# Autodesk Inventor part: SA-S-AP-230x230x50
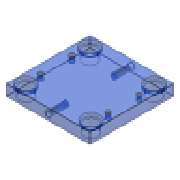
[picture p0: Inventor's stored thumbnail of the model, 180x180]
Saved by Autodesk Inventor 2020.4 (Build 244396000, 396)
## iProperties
Created: 2019-01
Part Number: SA-S-AP-230x230x50
Material: S 55 C
Description: Cavity Plate
Document SubType Name: Modeling
Designer: mel
Standard Revision: 1
Manufacturer: FUTABA
Language: fr-FR
Size Designation: 230x230x50
Categories: <MemberInstance><Categories><Category DisplayName="Moule" InternalName="349578f2-f4d4-4954-8c09-8e99297a61c0" Mnemonic="MOLD"><Category DisplayName="Plaque de m
Density: 7.85 g/cm^3
Appearance: Clear - Blue
IsCustomPart: 1
Author: mel
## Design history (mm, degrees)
sketch "Sketch1"
  geometry: L1 (-115, 115)-(115, 115); L2 (115, 115)-(115, -115); L3 (115, -115)-(-115, -115); L4 (-115, -115)-(-115, 115); 3 further points
  constraints: 8 end point, 2 midpoint, 2 parallel, 1 horizontal, 1 horizontal alignment, 1 perpendicular, 1 vertical alignment
  dimensions: "d123" = 230 distance between parallel lines of L2 L4 (= W_); "d124" = 230 distance between parallel lines of L3 L1 (= L)
extrude "Extrusion1" new body sketch "Sketch1" distance "d20" = 50 (= H_); taper "d30" = 0 deg
sketch "Sketch2"
  geometry: 4 further points
  constraints: 1 horizontal alignment
  dimensions: "d125" = 92.5 horizontal distance of point (0, 0) point (-92.5, 53) (= 0.5 x S1_W); "d126" = 53 vertical distance of point (0, 0) point (-92.5, 53) (= 0.5 x S1_L); "d127" = 92 horizontal distance of point (0, 0) point (-92, 92) (= 0.5 x GB_W); "d128" = 92 horizontal distance of point (0, 0) point (-92, 92) (= 0.5 x GB_L); "d129" = 92 horizontal distance of point (0, 0) point (92, 92) (= 0.5 x GB_W)
sketch "Sketch3"
  geometry: L1 (230, 0)-(0, 0) reference; 3 further points
  constraints: 1 midpoint, 1 vertical alignment
  dimensions: "d169" = 25 distance from line of L1 point (115, 25) (= 0.5 x H_)
hole "Hole1" sketch "Sketch3" at (115, 25) diameter "d170" = 13.835; stored, may be unused: countersink angle "d174" = 90 deg, drill point angle "d176" = 118 deg; dims "d171" = 29 (= le), "d172" = 4, "d173" = 2, "d175" = 39 (= ke)
sketch "Sketch4"
  geometry: L1 (0, 0)-(230, 0) reference; 4 further points
  constraints: 2 midpoint, 2 vertical alignment
  dimensions: "d177" = 25 distance from line of L1 point (115, -25) (= 0.5 x H_)
hole "Hole2" sketch "Sketch4" at (115, -25) diameter "d178" = 13.835; stored, may be unused: countersink angle "d182" = 90 deg, drill point angle "d184" = 118 deg; dims "d179" = 29 (= le), "d180" = 4, "d181" = 2, "d183" = 39 (= ke)
hole "Hole3" sketch "Sketch2" diameter "d130" = 30 (= GB_d1); stored, may be unused: countersink angle "d134" = 90 deg, drill point angle "d136" = 0 deg; dims "d131" = 6, "d132" = 36 (= GB_d2), "d133" = 8 (= GB_k), "d135" = 50 (= H_)
pattern_linear "Rectangular Pattern1" dims "d159" = 184 (computed from GB_L, Nl)
hole "Hole4" sketch "Sketch2" diameter "d137" = 30 (= GB_d1); stored, may be unused: countersink angle "d141" = 90 deg, drill point angle "d143" = 0 deg; dims "d138" = 6, "d139" = 36 (= GB_d2), "d140" = 8 (= GB_k), "d142" = 50 (= H_)
pattern_linear "Rectangular Pattern2" dims "d162" = 182 (computed from GB_L2, GB_L1, Nl)
hole "Hole5" sketch "Sketch2" diameter "d144" = 10.106; stored, may be unused: countersink angle "d148" = 90 deg, drill point angle "d150" = 118 deg; dims "d145" = 15 (= H_l), "d146" = 36 (= GB_d2), "d147" = 8 (= GB_k), "d149" = 24 (= H_u)
pattern_linear "Rectangular Pattern3" dims "d153" = 106 (computed from S1_L, Ns), "d156" = 185 (computed from S1_W, Nw)
chamfer "Chamfer1" distance "d185" = 0.5; stored, may be unused: second distance "d186" = 2, angle "d187" = 45 deg
feature "Sculpter1"
body "Solid1"
feature "Surface1"
body "Srf1"
other parameters: "L" = 230 [user parameter; used in 1 equation term], "W_" = 230 [user parameter; used in 1 equation term], "H_" = 50 [user parameter; used in 5 equation terms], "GB_W" = 184 [user parameter; used in 2 equation terms], "GB_d1" = 30 [user parameter; used in 2 equation terms], "GB_d2" = 36 [user parameter; used in 3 equation terms], "GB_k" = 8 [user parameter; used in 3 equation terms], "S1_L" = 106 [user parameter; used in 2 equation terms], "S1_W" = 185 [user parameter; used in 2 equation terms], "GB_L1" = 92 [user parameter; used in 1 equation term], "GB_L" = 184 [user parameter; used in 2 equation terms], "le" = 29 [user parameter; used in 2 equation terms], "ke" = 39 [user parameter; used in 2 equation terms], "H_l" = 15 [user parameter; used in 1 equation term], "H_u" = 24 [user parameter; used in 1 equation term]
